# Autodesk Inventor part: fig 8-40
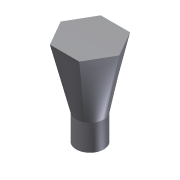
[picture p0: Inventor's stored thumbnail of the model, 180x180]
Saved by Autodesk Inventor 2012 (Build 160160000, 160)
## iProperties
Created: 2004-05
Part Number: fig 8-40
Document SubType Name: Modeling
Designer: CADCIM Technologies
Manufacturer: Standard
Standards Organization: Custom
Density: 1 g/cm^3
Material: Default
Author: CADCIM Technologies
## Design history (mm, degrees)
sketch "Sketch1"
  geometry: C1 r 16.344 at (0, 0)
  constraints: 1 centre point
extrude "Extrusion1" new body sketch "Sketch1" distance "d0" = 30.75; taper "d1" = 0 deg
workplane "Work Plane1"
sketch "Sketch2"
  geometry: L1 (34.788, 0)-(17.394, -30.128); L2 (17.394, -30.128)-(-17.394, -30.128); L3 (-17.394, -30.128)-(-34.788, 0); L4 (-34.788, 0)-(-17.394, 30.128); L5 (-17.394, 30.128)-(17.394, 30.128); L6 (17.394, 30.128)-(34.788, 0); 2 further points
  constraints: 12 end point, 1 coincident, 12 other
loft "Loft2" sketch "Sketch2" dims "d7" = 0, "d8" = 90 deg, "d9" = 0, "d10" = 90 deg
  node "Edges2"
body "Solid1"
other parameters: "d2" = 75
